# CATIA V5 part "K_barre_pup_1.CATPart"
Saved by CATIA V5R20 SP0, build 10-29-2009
Part number: barre_pup_1
Bounding box of the stored display mesh (mm): x -51.425 to -42.84, y -5.496 to 191.144, z 33.478 to 95.319
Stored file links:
  G:\Khaled_CFAO_2011\ST2M\ST2M_GR2\gcausse\Khaled\CAD_ThinkMotion\K_barre_pup_1.CATPart
  C:\Documents and Settings\gcausse\Bureau\video thinkmotio\assemblage_gcausse\pupitre_think.CATProduct
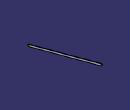
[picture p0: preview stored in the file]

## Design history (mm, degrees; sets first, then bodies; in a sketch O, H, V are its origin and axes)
Set1
  Sketch1 on Plane1, origin (-53.7378, 0, 6.6108), H (0, 1, 0), V (0.1221, 0, 0.9925)
    line L1 (187.933, 89.1543) -> (-3.7149, 31.961)
    arc A1 centre (-3, 29.5654) radius 2.5 from (-3.7149, 31.961) to (-2.2851, 27.1698) ccw
    point P3 (-3, 29.5654)
    line L2 (-2.2851, 27.1698) -> (189.3629, 84.3631)
    arc A2 centre (188.6479, 86.7587) radius 2.5 from (189.3629, 84.3631) to (187.933, 89.1543) ccw
    point P6 (188.6479, 86.7587)
    reference projected point E1 (188.6479, 86.7587) from Point1
    reference projected point E2 (-3, 29.5654) from Point2
    reference projected line E3 (188.6479, 86.7587) -> (-3, 29.5654) from Line1
    distance L1 L2 = 5
    tangency: A1 L1, L2 A1, A2 L2, A2 L1
    coincidence: P6 E1, P3 E2
    parallelism: L1 E3
Set2
  Plane1: linked copy from another document
  Point1: linked copy from another document
  Point2: linked copy from another document
  Line1: linked copy from another document
Body1 (main body)
  Pad1: profile Sketch1, direction (0.9925, 0, -0.1221), length -1
  Sketch2 on end face of Pad1, origin (-44.8052, 172.3025, 87.4126), H (0.1221, 0, 0.9925), V (0, 1, 0)
    point P1 (5.4708, 16.3454)
    reference projected point E1 (5.4708, 16.3454) from Point1
    coincidence: P1 E1
  Hole1: placed by Sketch2, at (-44.1372, 188.6479, 92.8425) direction (0.9925, 0, -0.1221), diameter 1, depth 1
  Sketch3 on end face of Pad1, origin (-48.3485, 74.8319, 58.6093), H (0.1221, 0, 0.9925), V (0, 1, 0)
    point P1 (-22.702, -77.8319)
    reference projected point E1 (-22.702, -77.8319) from Point2
    coincidence: P1 E1
  Hole2: placed by Sketch3, at (-51.1204, -3, 36.0771) direction (0.9925, 0, -0.1221), diameter 1, depth 1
